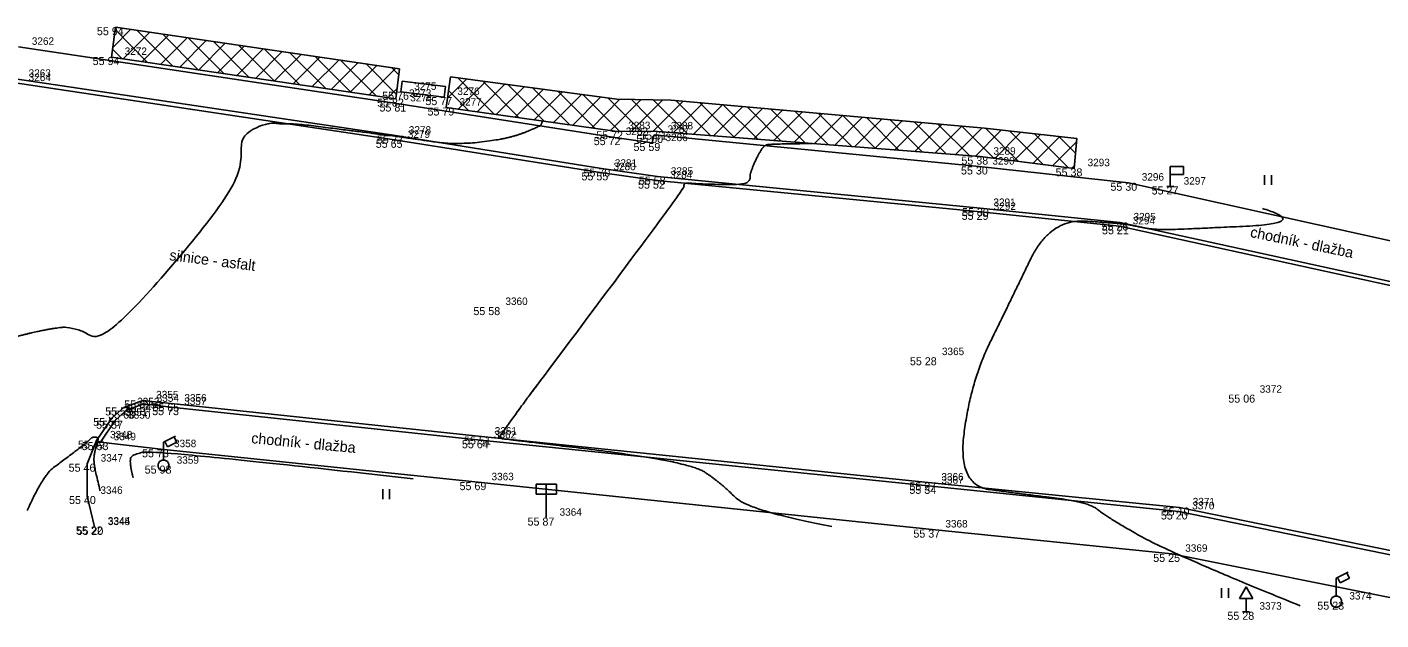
# Model space of a CAD drawing. Extents: x -704017 to -701500, y -1008977 to -1008450.
# Drawn here: x -702231.2 to -702180.5, y -1008822.8 to -1008800.5 of the extents above; entities that cross this region are included whole.
import ezdxf

# ---------------------------------------------------------------- set-up
doc = ezdxf.new("R2010")
doc.units = 0
for name, color, linetype in [('Z_body', 7, 'Continuous'), ('Z_body_cisla', 7, 'Continuous'), ('Z_body_vysky', 7, 'Continuous'), ('Z_chodnik', 7, 'Continuous'), ('Z_dopravni_znaceni', 7, 'Continuous'), ('Z_komunikace', 7, 'Continuous'), ('Z_obruby', 7, 'Continuous'), ('Z_oploceni', 7, 'Continuous'), ('Z_popis', 7, 'Continuous'), ('Z_site_znaky_pilire', 7, 'Continuous'), ('Z_site_znaky_VO', 7, 'Continuous'), ('Z_vrstevnice_vedlejsi', 7, 'Continuous'), ('Z_zelen_souvisla_srafy', 7, 'Continuous')]:
    doc.layers.add(name, color=color, linetype=linetype)

# ---------------------------------------------------------------- blocks, each defined once
blk = doc.blocks.new('POINT_DISPLAY')
blk.add_line((0, 0), (0, 0))
blk = doc.blocks.new('Z306')
for p, q in [((-0.13, 0.17), (-0.13, -0.2)), ((0.13, 0.17), (0.13, -0.2))]:
    blk.add_line(p, q)
blk = doc.blocks.new('Z13')
for p, q in [((0, 0.88), (0.45, 1.1)), ((0.4, 1.07), (0.5, 0.88)), ((0, 0.2), (0, 0.88)), ((0.15, 0.7), (0.05, 0.9)), ((0.5, 0.88), (0.15, 0.7)), ((-0.2, 0.05), (-0.15, 0.15)), ((-0.2, -0.05), (-0.2, 0.05)), ((-0.15, 0.15), (-0.05, 0.2)), ((-0.05, 0.2), (0.05, 0.2)), ((0.05, 0.2), (0.15, 0.15)), ((0.15, 0.15), (0.2, 0.05)), ((0.2, 0.05), (0.2, -0.05)), ((-0.15, -0.15), (-0.2, -0.05)), ((-0.05, -0.2), (-0.15, -0.15)), ((0.05, -0.2), (-0.05, -0.2)), ((0.15, -0.15), (0.05, -0.2)), ((0.2, -0.05), (0.15, -0.15))]:
    blk.add_line(p, q)
blk = doc.blocks.new('Z527')
for p, q in [((0, 0.93), (-0.25, 0.5)), ((0.25, 0.5), (0, 0.93)), ((-0.25, 0.5), (0.25, 0.5)), ((-0.13, 0), (0.13, 0)), ((0, 0), (0, 0.5))]:
    blk.add_line(p, q)
blk = doc.blocks.new('Z524')
for p, q in [((0, 0), (0, 0.75)), ((0, 0.75), (0.5, 0.75)), ((0.5, 0.75), (0.5, 0.45)), ((-0.13, 0), (0.13, 0)), ((0.5, 0.45), (0, 0.45))]:
    blk.add_line(p, q)
blk = doc.blocks.new('Z57')
for p, q in [((-0.38, 1.25), (0.38, 1.25)), ((-0.38, 0.88), (-0.38, 1.25)), ((0, 0), (0, 1.25)), ((0.38, 1.25), (0.38, 0.88)), ((0.38, 0.88), (-0.38, 0.88))]:
    blk.add_line(p, q)

msp = doc.modelspace()

# ---------------------------------------------------------------- linework, layer by layer
at = {"layer": 'Z_chodnik'}
for p, q in [((-702231.55, -1008801.28), (-702217.37, -1008803.4)), ((-702217.37, -1008803.4), (-702209.29, -1008804.66)), ((-702209.29, -1008804.66), (-702207.8, -1008804.88)), ((-702207.8, -1008804.88), (-702207.72, -1008804.58)), ((-702207.72, -1008804.58), (-702195.55, -1008805.76)), ((-702195.55, -1008805.76), (-702189.95, -1008806.37)), ((-702189.95, -1008806.37), (-702176.31, -1008809.39)), ((-702228.48, -1008816.09), (-702228.62, -1008816.03)), ((-702228.48, -1008816.09), (-702226.22, -1008816.36)), ((-702226.22, -1008816.36), (-702214.32, -1008817.59)), ((-702214.32, -1008817.59), (-702197.31, -1008819.37)), ((-702197.31, -1008819.37), (-702188.32, -1008820.28)), ((-702188.32, -1008820.28), (-702177.42, -1008822.46))]:
    msp.add_line(p, q, dxfattribs=at)
at = {"layer": 'Z_komunikace'}
for p, q in [((-702231.67, -1008802.63), (-702217.46, -1008804.76)), ((-702217.46, -1008804.76), (-702209.75, -1008805.98)), ((-702209.75, -1008805.98), (-702207.63, -1008806.29)), ((-702207.63, -1008806.29), (-702195.5, -1008807.46)), ((-702195.5, -1008807.46), (-702190.29, -1008808)), ((-702190.29, -1008808), (-702176.63, -1008810.99)), ((-702227.6, -1008814.79), (-702226.89, -1008814.53)), ((-702226.89, -1008814.53), (-702225.83, -1008814.64)), ((-702228.05, -1008815.19), (-702227.6, -1008814.79)), ((-702225.83, -1008814.64), (-702214.2, -1008815.88)), ((-702228.62, -1008816.03), (-702228.05, -1008815.19)), ((-702228.97, -1008816.9), (-702228.62, -1008816.03)), ((-702214.2, -1008815.88), (-702197.46, -1008817.6)), ((-702228.98, -1008818.11), (-702228.97, -1008816.9)), ((-702197.46, -1008817.6), (-702188.04, -1008818.54)), ((-702228.7, -1008819.27), (-702228.98, -1008818.11)), ((-702188.04, -1008818.54), (-702176.69, -1008820.85)), ((-702228.7, -1008819.25), (-702228.7, -1008819.27))]:
    msp.add_line(p, q, dxfattribs=at)
at = {"layer": 'Z_obruby'}
for p, q in [((-702231.67, -1008802.47), (-702217.42, -1008804.6)), ((-702217.42, -1008804.6), (-702209.7, -1008805.84)), ((-702209.7, -1008805.84), (-702207.6, -1008806.14)), ((-702207.6, -1008806.14), (-702195.51, -1008807.32)), ((-702195.51, -1008807.32), (-702190.26, -1008807.86)), ((-702190.26, -1008807.86), (-702176.58, -1008810.85)), ((-702227.94, -1008815.29), (-702227.51, -1008814.91)), ((-702227.51, -1008814.91), (-702226.87, -1008814.66)), ((-702226.87, -1008814.66), (-702225.84, -1008814.78)), ((-702225.84, -1008814.78), (-702214.23, -1008816.02)), ((-702228.48, -1008816.09), (-702227.94, -1008815.29)), ((-702214.23, -1008816.02), (-702197.46, -1008817.73)), ((-702197.46, -1008817.73), (-702188.06, -1008818.69)), ((-702188.06, -1008818.69), (-702176.73, -1008821.01))]:
    msp.add_line(p, q, dxfattribs=at)
at = {"layer": 'Z_oploceni'}
for p, q in [((-702227.91, -1008800.54), (-702228.07, -1008801.66)), ((-702228.07, -1008801.66), (-702217.41, -1008803.22)), ((-702215.52, -1008803.55), (-702209.2, -1008804.44)), ((-702209.2, -1008804.44), (-702207.6, -1008804.45)), ((-702207.6, -1008804.45), (-702195.51, -1008805.39)), ((-702195.51, -1008805.39), (-702191.98, -1008805.83))]:
    msp.add_line(p, q, dxfattribs=at)
at = {"layer": 'Z_site_znaky_pilire'}
for p, q in [((-702217.22, -1008802.96), (-702217.17, -1008802.56)), ((-702217.17, -1008802.56), (-702215.55, -1008802.76)), ((-702215.6, -1008803.16), (-702215.55, -1008802.76)), ((-702217.22, -1008802.96), (-702215.6, -1008803.16))]:
    msp.add_line(p, q, dxfattribs=at)
at = {"layer": 'Z_vrstevnice_vedlejsi'}
for points in [[(-702237.332, -1008814.524), (-702234.023, -1008813.005), (-702233.849, -1008812.762), (-702234.148, -1008812.695), (-702233.289, -1008812.551), (-702229.929, -1008811.708), (-702229.264, -1008811.892), (-702228.23, -1008812.354), (-702222.849, -1008806.003), (-702223.381, -1008803.873), (-702217.427, -1008804.627), (-702216.723, -1008804.725), (-702215.214, -1008804.954), (-702213.186, -1008804.731), (-702211.983, -1008804.24), (-702211.96, -1008804.184), (-702211.909, -1008804.059)], [(-702201.07, -1008819.253), (-702204.22, -1008818.647), (-702205.167, -1008817.666), (-702206.404, -1008816.818), (-702213.215, -1008815.989), (-702213.503, -1008815.952), (-702213.471, -1008815.751), (-702206.781, -1008806.842), (-702206.575, -1008806.392), (-702206.528, -1008806.384), (-702204.146, -1008806.477), (-702204.157, -1008806.031), (-702203.663, -1008804.973), (-702203.324, -1008804.915), (-702201.818, -1008804.9)], [(-702183.518, -1008822.222), (-702188.32, -1008820.28), (-702190.781, -1008818.89), (-702191.417, -1008818.347), (-702193.927, -1008818.034), (-702196.352, -1008817.711), (-702195.873, -1008813.848), (-702194.376, -1008810.806), (-702192.895, -1008807.73), (-702190.266, -1008807.888), (-702189.715, -1008807.985), (-702189.016, -1008808.132), (-702187.935, -1008808.115), (-702183.13, -1008807.88), (-702184.931, -1008807.333)], [(-702231.223, -1008818.649), (-702230.634, -1008817.345), (-702229.832, -1008816.744), (-702228.894, -1008816.035), (-702228.808, -1008815.9), (-702228.539, -1008815.91), (-702228.585, -1008816.045), (-702228.69, -1008816.437), (-702228.751, -1008816.905), (-702228.487, -1008817.913)], [(-702216.761, -1008817.462), (-702226.212, -1008816.409), (-702227.326, -1008816.52), (-702227.381, -1008816.939), (-702227.254, -1008817.422)]]:
    msp.add_open_spline(points, degree=2, dxfattribs=at)
at = {"layer": 'Z_zelen_souvisla_srafy'}
for p, q in [((-702228.02, -1008801.3), (-702227.34, -1008800.62)), ((-702227.92, -1008800.64), (-702226.71, -1008801.86)), ((-702227.91, -1008800.54), (-702217.27, -1008802.1)), ((-702227.63, -1008801.72), (-702226.63, -1008800.73)), ((-702227.1, -1008800.66), (-702225.76, -1008802)), ((-702226.92, -1008801.83), (-702225.92, -1008800.83)), ((-702226.14, -1008800.8), (-702224.81, -1008802.14)), ((-702226.21, -1008801.93), (-702225.21, -1008800.93)), ((-702225.5, -1008802.04), (-702224.51, -1008801.04)), ((-702225.19, -1008800.94), (-702223.85, -1008802.28)), ((-702224.79, -1008802.14), (-702223.8, -1008801.14)), ((-702224.24, -1008801.08), (-702222.9, -1008802.42)), ((-702224.08, -1008802.24), (-702223.09, -1008801.25)), ((-702223.29, -1008801.22), (-702221.95, -1008802.56)), ((-702228.03, -1008801.36), (-702227.66, -1008801.72)), ((-702223.37, -1008802.35), (-702222.38, -1008801.35)), ((-702222.66, -1008802.45), (-702221.67, -1008801.45)), ((-702222.33, -1008801.36), (-702221, -1008802.7)), ((-702221.96, -1008802.55), (-702220.96, -1008801.56)), ((-702221.38, -1008801.5), (-702220.04, -1008802.83)), ((-702221.25, -1008802.66), (-702220.25, -1008801.66)), ((-702220.54, -1008802.76), (-702219.54, -1008801.77)), ((-702220.43, -1008801.64), (-702219.09, -1008802.97)), ((-702219.48, -1008801.78), (-702218.14, -1008803.11)), ((-702219.83, -1008802.87), (-702218.83, -1008801.87)), ((-702219.12, -1008802.97), (-702218.12, -1008801.97)), ((-702218.52, -1008801.91), (-702217.39, -1008803.05)), ((-702218.41, -1008803.07), (-702217.41, -1008802.08)), ((-702217.57, -1008802.05), (-702217.3, -1008802.33)), ((-702217.27, -1008802.1), (-702217.41, -1008803.22)), ((-702217.7, -1008803.18), (-702217.36, -1008802.84)), ((-702215.52, -1008803.55), (-702215.36, -1008802.4)), ((-702215.47, -1008803.2), (-702214.75, -1008802.48)), ((-702215.36, -1008802.4), (-702209.13, -1008803.24)), ((-702215.09, -1008802.43), (-702213.72, -1008803.8)), ((-702215.07, -1008803.61), (-702214.04, -1008802.58)), ((-702214.36, -1008803.71), (-702213.32, -1008802.67)), ((-702214.15, -1008802.56), (-702212.78, -1008803.94)), ((-702213.65, -1008803.81), (-702212.6, -1008802.77)), ((-702213.21, -1008802.69), (-702211.83, -1008804.07)), ((-702212.27, -1008802.82), (-702210.88, -1008804.2)), ((-702215.43, -1008802.91), (-702214.67, -1008803.67)), ((-702212.93, -1008803.91), (-702211.89, -1008802.87)), ((-702212.22, -1008804.01), (-702211.17, -1008802.97)), ((-702211.51, -1008804.12), (-702210.45, -1008803.06)), ((-702211.33, -1008802.94), (-702209.94, -1008804.34)), ((-702210.79, -1008804.22), (-702209.74, -1008803.16)), ((-702210.39, -1008803.07), (-702209.02, -1008804.44)), ((-702210.08, -1008804.32), (-702209.01, -1008803.24)), ((-702209.45, -1008803.2), (-702208.2, -1008804.45)), ((-702209.37, -1008804.42), (-702208.21, -1008803.25)), ((-702209.13, -1008803.24), (-702207.09, -1008803.27)), ((-702208.58, -1008803.25), (-702207.37, -1008804.47)), ((-702208.58, -1008804.44), (-702207.4, -1008803.26)), ((-702207.78, -1008804.45), (-702206.64, -1008803.31)), ((-702207.76, -1008803.26), (-702206.48, -1008804.54)), ((-702207.09, -1008803.27), (-702195.35, -1008804.33)), ((-702206.92, -1008803.28), (-702205.6, -1008804.61)), ((-702206.03, -1008803.36), (-702204.72, -1008804.67)), ((-702207.01, -1008804.5), (-702205.89, -1008803.38)), ((-702206.25, -1008804.55), (-702205.15, -1008803.44)), ((-702205.5, -1008804.61), (-702204.4, -1008803.51)), ((-702205.14, -1008803.45), (-702203.84, -1008804.74)), ((-702204.75, -1008804.67), (-702203.65, -1008803.58)), ((-702204.24, -1008803.53), (-702202.96, -1008804.81)), ((-702203.99, -1008804.73), (-702202.91, -1008803.65)), ((-702203.35, -1008803.61), (-702202.07, -1008804.88)), ((-702203.24, -1008804.79), (-702202.16, -1008803.71)), ((-702202.48, -1008804.85), (-702201.42, -1008803.78)), ((-702202.45, -1008803.69), (-702201.19, -1008804.95)), ((-702201.73, -1008804.91), (-702200.67, -1008803.85)), ((-702201.56, -1008803.77), (-702200.31, -1008805.02)), ((-702200.66, -1008803.85), (-702199.43, -1008805.09)), ((-702200.97, -1008804.97), (-702199.93, -1008803.92)), ((-702200.22, -1008805.02), (-702199.18, -1008803.98)), ((-702199.77, -1008803.93), (-702198.55, -1008805.15)), ((-702199.46, -1008805.08), (-702198.43, -1008804.05)), ((-702198.88, -1008804.01), (-702197.67, -1008805.22)), ((-702198.71, -1008805.14), (-702197.69, -1008804.12)), ((-702197.98, -1008804.09), (-702196.78, -1008805.29)), ((-702197.96, -1008805.2), (-702196.94, -1008804.19)), ((-702197.2, -1008805.26), (-702196.2, -1008804.25)), ((-702197.09, -1008804.17), (-702195.9, -1008805.36)), ((-702196.45, -1008805.32), (-702195.45, -1008804.32)), ((-702196.19, -1008804.25), (-702194.99, -1008805.45)), ((-702195.35, -1008804.33), (-702191.89, -1008804.71)), ((-702195.3, -1008804.34), (-702194.07, -1008805.57)), ((-702195.69, -1008805.38), (-702194.72, -1008804.4)), ((-702194.96, -1008805.46), (-702193.98, -1008804.48)), ((-702194.39, -1008804.44), (-702193.14, -1008805.69)), ((-702194.24, -1008805.55), (-702193.25, -1008804.56)), ((-702193.52, -1008805.64), (-702192.52, -1008804.64)), ((-702193.47, -1008804.54), (-702192.21, -1008805.8)), ((-702192.79, -1008805.73), (-702191.9, -1008804.84)), ((-702192.56, -1008804.64), (-702191.93, -1008805.26)), ((-702191.89, -1008804.71), (-702191.98, -1008805.83)), ((-702192.07, -1008805.82), (-702191.97, -1008805.72))]:
    msp.add_line(p, q, dxfattribs=at)

# ---------------------------------------------------------------- block references
at = {"layer": 'Z_body'}
for p in [(-702227.91, -1008800.54), (-702228.07, -1008801.66), (-702217.41, -1008803.22), (-702217.22, -1008802.96), (-702215.6, -1008803.16), (-702217.37, -1008803.4), (-702215.52, -1008803.55), (-702217.46, -1008804.76), (-702217.42, -1008804.6), (-702209.29, -1008804.66), (-702209.2, -1008804.44), (-702207.8, -1008804.88), (-702207.72, -1008804.58), (-702207.6, -1008804.45), (-702195.51, -1008805.39), (-702209.7, -1008805.84), (-702195.55, -1008805.76), (-702191.98, -1008805.83), (-702209.75, -1008805.98), (-702207.63, -1008806.29), (-702207.6, -1008806.14), (-702189.95, -1008806.37), (-702188.38, -1008806.51), (-702195.51, -1008807.32), (-702195.5, -1008807.46), (-702190.26, -1008807.86), (-702190.29, -1008808), (-702213.8, -1008811.03), (-702197.44, -1008812.91), (-702226.89, -1008814.53), (-702185.53, -1008814.31), (-702227.6, -1008814.79), (-702227.51, -1008814.91), (-702226.87, -1008814.66), (-702225.84, -1008814.78), (-702225.83, -1008814.64), (-702228.05, -1008815.19), (-702227.94, -1008815.29), (-702228.62, -1008816.03), (-702214.23, -1008816.02), (-702214.2, -1008815.88), (-702228.48, -1008816.09), (-702226.22, -1008816.36), (-702228.97, -1008816.9), (-702226.12, -1008816.97), (-702214.32, -1008817.59), (-702197.46, -1008817.6), (-702197.46, -1008817.73), (-702228.98, -1008818.11), (-702188.04, -1008818.54), (-702211.77, -1008818.92), (-702188.06, -1008818.69), (-702228.7, -1008819.25), (-702228.7, -1008819.27), (-702197.31, -1008819.37), (-702188.32, -1008820.28), (-702182.17, -1008822.07), (-702185.54, -1008822.45)]:
    msp.add_blockref('POINT_DISPLAY', p, dxfattribs=at)
at = {"layer": 'Z_dopravni_znaceni'}
for name, p in [('Z524', (-702188.38, -1008806.51)), ('Z57', (-702211.77, -1008818.92)), ('Z527', (-702185.54, -1008822.45))]:
    msp.add_blockref(name, p, dxfattribs=at)
at = {"layer": 'Z_popis'}
for p in [(-702184.72, -1008806.25), (-702217.77, -1008818.03), (-702186.33, -1008821.73)]:
    msp.add_blockref('Z306', p, dxfattribs=at)
at = {"layer": 'Z_site_znaky_VO'}
for p in [(-702226.12, -1008816.97), (-702182.17, -1008822.07)]:
    msp.add_blockref('Z13', p, dxfattribs=at)

# ---------------------------------------------------------------- texts
at = {"layer": 'Z_body_cisla'}
for s, p in [('3262', (-702231.05, -1008801.2)), ('3272', (-702227.57, -1008801.58)), ('3263', (-702231.17, -1008802.4)), ('3264', (-702231.17, -1008802.56)), ('3273', (-702216.91, -1008803.15)), ('3275', (-702216.72, -1008802.89)), ('3276', (-702215.1, -1008803.08)), ('3274', (-702216.87, -1008803.32)), ('3277', (-702215.02, -1008803.48)), ('3278', (-702216.92, -1008804.53)), ('3282', (-702208.79, -1008804.58)), ('3283', (-702208.7, -1008804.36)), ('3287', (-702207.22, -1008804.5)), ('3288', (-702207.1, -1008804.37)), ('3279', (-702216.96, -1008804.69)), ('3286', (-702207.3, -1008804.81)), ('3289', (-702195.01, -1008805.32)), ('3280', (-702209.25, -1008805.9)), ('3281', (-702209.2, -1008805.77)), ('3285', (-702207.1, -1008806.07)), ('3290', (-702195.05, -1008805.69)), ('3293', (-702191.48, -1008805.75)), ('3284', (-702207.13, -1008806.21)), ('3296', (-702189.45, -1008806.29)), ('3297', (-702187.88, -1008806.44)), ('3291', (-702195.01, -1008807.24)), ('3292', (-702195, -1008807.39)), ('3294', (-702189.79, -1008807.93)), ('3295', (-702189.76, -1008807.78)), ('3360', (-702213.3, -1008810.95)), ('3365', (-702196.94, -1008812.83)), ('3372', (-702185.03, -1008814.24)), ('3352', (-702227.1, -1008814.71)), ('3355', (-702226.39, -1008814.45)), ('3354', (-702226.37, -1008814.58)), ('3357', (-702225.34, -1008814.7)), ('3356', (-702225.33, -1008814.57)), ('3351', (-702227.55, -1008815.11)), ('3350', (-702227.44, -1008815.21)), ('3353', (-702227.01, -1008814.83)), ('3361', (-702213.7, -1008815.81)), ('3348', (-702228.12, -1008815.95)), ('3349', (-702227.98, -1008816.02)), ('3358', (-702225.72, -1008816.28)), ('3362', (-702213.73, -1008815.95)), ('3347', (-702228.47, -1008816.82)), ('3359', (-702225.62, -1008816.9)), ('3363', (-702213.82, -1008817.52)), ('3366', (-702196.96, -1008817.53)), ('3367', (-702196.96, -1008817.65)), ('3346', (-702228.48, -1008818.03)), ('3364', (-702211.27, -1008818.85)), ('3370', (-702187.56, -1008818.61)), ('3371', (-702187.54, -1008818.46)), ('3344', (-702228.2, -1008819.18)), ('3345', (-702228.2, -1008819.2)), ('3368', (-702196.81, -1008819.29)), ('3369', (-702187.82, -1008820.2)), ('3373', (-702185.04, -1008822.37)), ('3374', (-702181.67, -1008821.99))]:
    msp.add_text(s, height=0.28, dxfattribs=at).set_placement(p)
at = {"layer": 'Z_body_vysky'}
for s, p in [('55 94', (-702228.61, -1008800.84)), ('55 94', (-702228.77, -1008801.96)), ('55 82', (-702218.11, -1008803.52)), ('55 76', (-702217.92, -1008803.26)), ('55 77', (-702216.3, -1008803.46)), ('55 81', (-702218.02, -1008803.7)), ('55 79', (-702216.22, -1008803.85)), ('55 65', (-702218.16, -1008805.06)), ('55 77', (-702218.12, -1008804.9)), ('55 72', (-702209.99, -1008804.96)), ('55 72', (-702209.9, -1008804.74)), ('55 59', (-702208.5, -1008805.18)), ('55 60', (-702208.395, -1008804.88)), ('55 61', (-702208.25, -1008804.75)), ('55 38', (-702196.21, -1008805.69)), ('55 70', (-702210.375, -1008806.14)), ('55 30', (-702196.225, -1008806.06)), ('55 38', (-702192.68, -1008806.13)), ('55 55', (-702210.45, -1008806.28)), ('55 52', (-702208.33, -1008806.59)), ('55 58', (-702208.3, -1008806.44)), ('55 30', (-702190.625, -1008806.67)), ('55 27', (-702189.08, -1008806.81)), ('55 30', (-702196.185, -1008807.62)), ('55 29', (-702196.2, -1008807.76)), ('55 26', (-702190.96, -1008808.16)), ('55 21', (-702190.94, -1008808.3)), ('55 58', (-702214.5, -1008811.33)), ('55 28', (-702198.14, -1008813.21)), ('55 62', (-702227.59, -1008814.83)), ('55 06', (-702186.205, -1008814.61)), ('55 59', (-702228.3, -1008815.09)), ('55 60', (-702228.185, -1008815.21)), ('55 64', (-702227.57, -1008814.96)), ('55 73', (-702226.54, -1008815.08)), ('55 65', (-702226.53, -1008814.94)), ('55 56', (-702228.75, -1008815.49)), ('55 57', (-702228.64, -1008815.59)), ('55 49', (-702229.32, -1008816.33)), ('55 64', (-702214.93, -1008816.32)), ('55 51', (-702214.85, -1008816.18)), ('55 53', (-702229.18, -1008816.39)), ('55 73', (-702226.92, -1008816.66)), ('55 46', (-702229.67, -1008817.2)), ('55 98', (-702226.82, -1008817.27)), ('55 69', (-702215.02, -1008817.89)), ('55 27', (-702198.16, -1008817.9)), ('55 34', (-702198.16, -1008818.03)), ('55 40', (-702229.655, -1008818.41)), ('55 10', (-702188.665, -1008818.84)), ('55 87', (-702212.47, -1008819.22)), ('55 20', (-702188.735, -1008818.99)), ('55 22', (-702229.4, -1008819.55)), ('55 20', (-702229.375, -1008819.57)), ('55 37', (-702198.01, -1008819.67)), ('55 25', (-702189.02, -1008820.58)), ('55 23', (-702182.87, -1008822.37)), ('55 28', (-702186.24, -1008822.75))]:
    msp.add_text(s, height=0.3, dxfattribs=at).set_placement(p)
at = {"layer": 'Z_popis'}
for s, rotation, p in [('chodník - dlažba', 348.3, (-702185.41, -1008808.4)), ('silnice - asfalt', 352.8, (-702225.91, -1008809.27)), ('chodník - dlažba', 354.6, (-702222.84, -1008816.13))]:
    msp.add_text(s, height=0.4, rotation=rotation, dxfattribs=at).set_placement(p)

doc.saveas('drawing.dxf')
